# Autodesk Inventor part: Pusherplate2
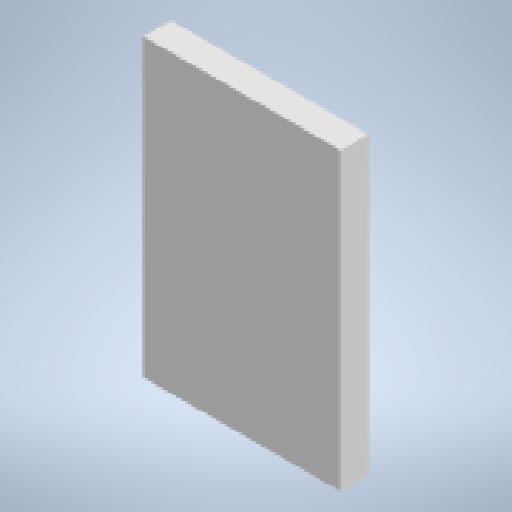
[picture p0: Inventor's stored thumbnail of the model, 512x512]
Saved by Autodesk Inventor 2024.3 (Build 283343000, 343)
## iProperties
Created: 2024-12
Part Number: Pusherplate2
Material: Generic
Document SubType Name: Modeling
Designer: ruhr
Density: 1 g/cm^3
Appearance: Default
Author: ruhr
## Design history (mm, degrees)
sketch "Sketch1"
  geometry: L1 (17.771, 26.636)-(17.771, -26.636); L2 (17.771, -26.636)-(-17.771, -26.636); L3 (-17.771, -26.636)-(-17.771, 26.636); L4 (-17.771, 26.636)-(17.771, 26.636); L5 (17.771, 26.636)-(-17.771, -26.636); L6 (17.771, -26.636)-(-17.771, 26.636); 1 further point
  constraints: 12 end point, 2 midpoint, 2 parallel, 1 perpendicular, 1 vertical
extrude "Extrusion1" new body sketch "Sketch1" distance "d0" = 5; taper "d1" = 0 deg
body "Solid1"
